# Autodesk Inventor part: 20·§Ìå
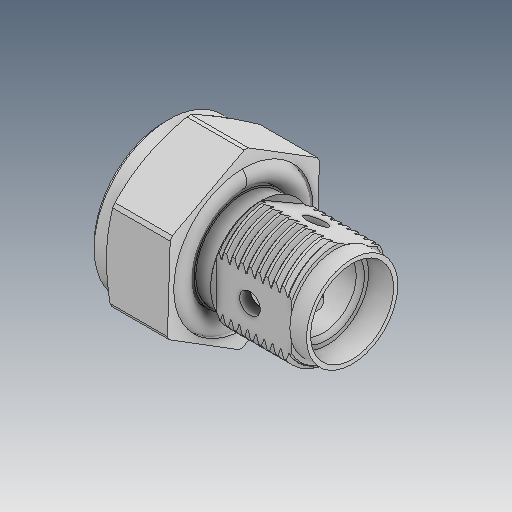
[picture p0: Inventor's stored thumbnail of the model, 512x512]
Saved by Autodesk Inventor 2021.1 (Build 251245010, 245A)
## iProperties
Created: 2019-04
Part Number: 20·§Ìå
Material: Ogólny
Document SubType Name: Modeling
Designer: user
Density: 1 g/cm^3
Appearance: Domyślna
Author: user
Revision Number: ÈÎºÎ
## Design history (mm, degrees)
feature "ÊäÈë1"
feature "ÊäÈë2"
node "Bryła1"
node "Bryła2"
